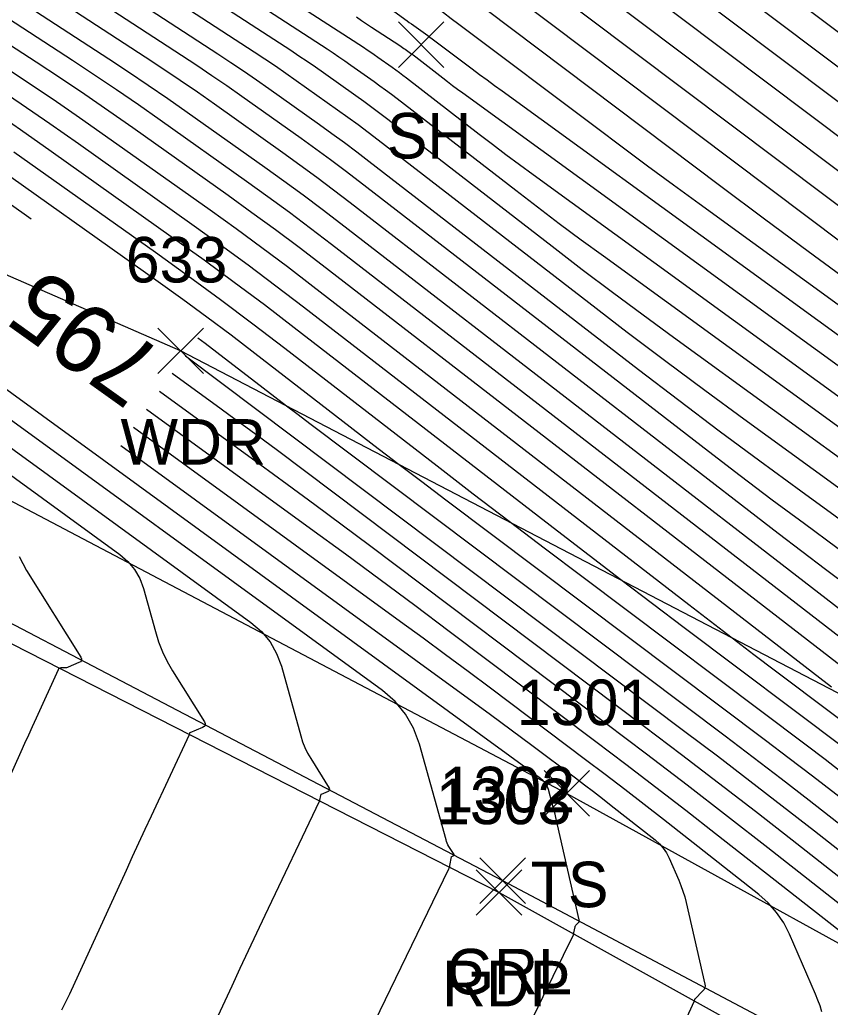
# Model space of a CAD drawing. Extents: x 1650836 to 1652450, y 332578 to 333908.
# Drawn here: x 1652211.55 to 1652247.14, y 332737.29 to 332780.66 of the extents above; entities that cross this region are included whole.
import ezdxf

# ---------------------------------------------------------------- set-up
doc = ezdxf.new("R2010")
doc.units = 0
for name, color, linetype in [('L_A', 7, 'Continuous'), ('L_I', 7, 'Continuous'), ('L_TIC', 7, 'Continuous'), ('LAWA', 7, 'Continuous'), ('LELB', 7, 'Continuous'), ('LSOGCMA', 7, 'Continuous'), ('LSOGCMA_T', 7, 'Continuous'), ('LSOGCMI', 7, 'Continuous'), ('P_A', 7, 'Continuous'), ('P_I', 7, 'Continuous'), ('P_TIC', 7, 'Continuous'), ('PET', 7, 'Continuous'), ('R_A', 7, 'Continuous'), ('R_I', 7, 'Continuous'), ('R_TIC', 7, 'Continuous'), ('RGR', 7, 'Continuous')]:
    doc.layers.add(name, color=color, linetype=linetype)

msp = doc.modelspace()

# ---------------------------------------------------------------- linework, layer by layer
at = {"layer": 'L_TIC'}
for points in [[(1652228.178, 332778.566), (1652230.178, 332780.566)], [(1652230.178, 332778.566), (1652228.178, 332780.566)], [(1652217.614, 332765.122), (1652219.614, 332767.122)], [(1652219.614, 332765.122), (1652217.614, 332767.122)], [(1652234.573, 332745.682), (1652236.573, 332747.682)], [(1652236.573, 332745.682), (1652234.573, 332747.682)]]:
    msp.add_lwpolyline(points, dxfattribs=at)
at = {"layer": 'LAWA'}
msp.add_lwpolyline([(1652408.76, 332665.713), (1652363.38, 332695.402), (1652324.46, 332714.991), (1652289.155, 332735.895), (1652253.497, 332747.946), (1652218.614, 332766.122), (1652198.198, 332775.017), (1652146.456, 332804.843), (1652136.841, 332807.592), (1652091.374, 332831.511), (1652057.601, 332848.138), (1652027.653, 332867.625)], dxfattribs=at)
at = {"layer": 'LELB'}
msp.add_lwpolyline([(1652023.441, 332859.649), (1652034.235, 332853.429), (1652052.246, 332842.357), (1652084.686, 332826.36), (1652123.711, 332804.04), (1652160.81, 332785.384), (1652195.281, 332767.897), (1652235.573, 332746.682), (1652255.289, 332735.81), (1652296.57, 332712.591), (1652348.8, 332686.345), (1652380.841, 332668.301), (1652404.073, 332656.539)], dxfattribs=at)
at = {"layer": 'LSOGCMA'}
for points in [[(1652207.289, 332796.117), (1652228.455, 332780.692), (1652228.555, 332780.619), (1652228.655, 332780.547), (1652228.756, 332780.475), (1652228.857, 332780.404), (1652229.261, 332780.119), (1652229.361, 332780.048), (1652229.462, 332779.976), (1652229.561, 332779.902), (1652229.66, 332779.829), (1652231.418, 332778.505), (1652231.744, 332778.261), (1652232.072, 332778.017), (1652232.4, 332777.776), (1652232.73, 332777.535), (1652253.597, 332762.371), (1652257.064, 332759.833), (1652260.514, 332757.272), (1652263.946, 332754.687), (1652267.36, 332752.078), (1652272.52, 332748.107)], [(1652250.989, 332750.892), (1652225.242, 332770.792), (1652224.318, 332771.499), (1652223.388, 332772.196), (1652222.45, 332772.884), (1652221.505, 332773.562), (1652217.711, 332776.256), (1652216.759, 332776.925), (1652215.801, 332777.584), (1652214.836, 332778.233), (1652213.865, 332778.873), (1652201.055, 332787.21)], [(1652254.883, 332736.054), (1652244.393, 332744.289), (1652242.627, 332745.668), (1652240.854, 332747.038), (1652239.074, 332748.398), (1652237.287, 332749.75), (1652226.901, 332757.565), (1652225.703, 332758.462), (1652224.502, 332759.355), (1652223.297, 332760.243), (1652222.088, 332761.126), (1652217.682, 332764.332)]]:
    msp.add_lwpolyline(points, dxfattribs=at)
at = {"layer": 'LSOGCMI'}
for points in [[(1652156.182, 332810.098), (1652168.54, 332801.315), (1652170.745, 332799.759), (1652172.961, 332798.219), (1652175.188, 332796.695), (1652177.426, 332795.187), (1652196.78, 332782.244), (1652197.703, 332781.629), (1652198.627, 332781.017), (1652199.554, 332780.407), (1652200.482, 332779.801), (1652204.2, 332777.381), (1652205.127, 332776.771), (1652206.047, 332776.152), (1652206.961, 332775.524), (1652207.868, 332774.887), (1652212.045, 332771.92)], [(1652211.623, 332803.175), (1652217.033, 332799.233), (1652218.387, 332798.25), (1652219.745, 332797.273), (1652221.107, 332796.301), (1652222.473, 332795.335), (1652230.674, 332789.557), (1652232.492, 332788.265), (1652234.299, 332786.96), (1652236.096, 332785.64), (1652237.883, 332784.306), (1652256.91, 332769.983), (1652257.734, 332769.367), (1652258.561, 332768.755), (1652259.391, 332768.148), (1652260.225, 332767.545), (1652263.567, 332765.145), (1652264.401, 332764.544), (1652265.235, 332763.941), (1652266.066, 332763.335)], [(1652211.433, 332801.854), (1652217.893, 332797.146), (1652219.455, 332796.013), (1652221.02, 332794.887), (1652222.59, 332793.766), (1652224.165, 332792.652), (1652230.472, 332788.209), (1652232.045, 332787.092), (1652233.608, 332785.962), (1652235.163, 332784.821), (1652236.708, 332783.667), (1652259.482, 332766.523), (1652259.982, 332766.149), (1652260.484, 332765.778), (1652260.988, 332765.409), (1652261.494, 332765.043), (1652263.522, 332763.586), (1652264.029, 332763.222), (1652264.535, 332762.855), (1652265.04, 332762.488), (1652265.544, 332762.12)], [(1652283.425, 332747.411), (1652264.19, 332761.511), (1652264.013, 332761.641), (1652263.835, 332761.77), (1652263.657, 332761.899), (1652263.478, 332762.028), (1652262.763, 332762.541), (1652262.585, 332762.67), (1652262.407, 332762.8), (1652262.23, 332762.931), (1652262.054, 332763.063), (1652235.533, 332783.027), (1652234.229, 332784.001), (1652232.917, 332784.964), (1652231.597, 332785.918), (1652230.27, 332786.86), (1652224.947, 332790.611), (1652223.618, 332791.551), (1652222.293, 332792.497), (1652220.971, 332793.448), (1652219.654, 332794.404), (1652211.167, 332800.588)], [(1652265.562, 332758.934), (1652263.87, 332760.236), (1652263.513, 332760.509), (1652263.153, 332760.78), (1652262.792, 332761.048), (1652262.428, 332761.314), (1652260.972, 332762.373), (1652260.608, 332762.638), (1652260.246, 332762.905), (1652259.884, 332763.174), (1652259.524, 332763.444), (1652234.359, 332782.387), (1652233.295, 332783.181), (1652232.226, 332783.967), (1652231.15, 332784.744), (1652230.068, 332785.512), (1652225.729, 332788.569), (1652224.645, 332789.336), (1652223.565, 332790.107), (1652222.488, 332790.882), (1652221.414, 332791.661), (1652210.191, 332799.84)], [(1652270.187, 332754.007), (1652264.784, 332758.165), (1652263.641, 332759.038), (1652262.493, 332759.903), (1652261.339, 332760.76), (1652260.179, 332761.609), (1652255.526, 332764.99), (1652254.365, 332765.837), (1652253.207, 332766.69), (1652252.053, 332767.547), (1652250.903, 332768.41), (1652233.184, 332781.748), (1652232.362, 332782.362), (1652231.535, 332782.969), (1652230.703, 332783.57), (1652229.866, 332784.164), (1652226.511, 332786.528), (1652225.673, 332787.121), (1652224.838, 332787.717), (1652224.005, 332788.316), (1652223.174, 332788.919), (1652209.215, 332799.092)], [(1652273.843, 332749.826), (1652265.697, 332756.094), (1652263.77, 332757.566), (1652261.833, 332759.025), (1652259.886, 332760.471), (1652257.929, 332761.904), (1652250.031, 332767.643), (1652248.097, 332769.055), (1652246.169, 332770.475), (1652244.246, 332771.903), (1652242.33, 332773.339), (1652232.009, 332781.108), (1652231.428, 332781.542), (1652230.844, 332781.971), (1652230.256, 332782.396), (1652229.665, 332782.816), (1652227.293, 332784.487), (1652226.701, 332784.906), (1652226.11, 332785.327), (1652225.521, 332785.751), (1652224.934, 332786.177), (1652208.765, 332797.96)], [(1652208.027, 332797.039), (1652226.695, 332783.434), (1652227.038, 332783.185), (1652227.383, 332782.937), (1652227.728, 332782.691), (1652228.075, 332782.445), (1652229.463, 332781.468), (1652229.809, 332781.222), (1652230.153, 332780.973), (1652230.495, 332780.722), (1652230.835, 332780.468), (1652236.874, 332775.922), (1652237.995, 332775.082), (1652239.12, 332774.246), (1652240.249, 332773.415), (1652241.38, 332772.589), (1652255.679, 332762.198), (1652258.433, 332760.183), (1652261.173, 332758.148), (1652263.899, 332756.095), (1652266.611, 332754.023), (1652273.182, 332748.967)], [(1652229.258, 332793.535), (1652231.078, 332792.253), (1652233.386, 332790.613), (1652235.681, 332788.956), (1652237.963, 332787.28), (1652240.232, 332785.586), (1652251.766, 332776.903), (1652253.237, 332775.802), (1652254.714, 332774.71), (1652256.197, 332773.625), (1652257.686, 332772.549), (1652263.655, 332768.262), (1652265.146, 332767.188), (1652266.635, 332766.111), (1652268.12, 332765.03), (1652269.603, 332763.946), (1652278.411, 332757.49), (1652280.207, 332756.153), (1652281.984, 332754.79), (1652283.741, 332753.403), (1652285.479, 332751.99), (1652294.014, 332744.946)], [(1652228.557, 332792.539), (1652230.876, 332790.905), (1652232.939, 332789.439), (1652234.99, 332787.958), (1652237.03, 332786.46), (1652239.057, 332784.946), (1652254.338, 332773.443), (1652255.485, 332772.584), (1652256.637, 332771.732), (1652257.794, 332770.887), (1652258.956, 332770.047), (1652263.611, 332766.703), (1652264.774, 332765.866), (1652265.935, 332765.026), (1652267.093, 332764.183), (1652268.25, 332763.337), (1652279.664, 332754.97), (1652281.251, 332753.789), (1652282.821, 332752.586), (1652284.373, 332751.36), (1652285.908, 332750.112), (1652293.336, 332743.982)], [(1652265.616, 332743.878), (1652264.402, 332744.786), (1652263.196, 332745.705), (1652258.389, 332749.404), (1652257.184, 332750.325), (1652255.973, 332751.237), (1652254.756, 332752.141), (1652253.532, 332753.037), (1652247.428, 332757.472), (1652246.006, 332758.514), (1652244.592, 332759.566), (1652243.185, 332760.628), (1652241.786, 332761.701), (1652226.474, 332773.537), (1652225.839, 332774.023), (1652225.199, 332774.502), (1652224.555, 332774.974), (1652223.905, 332775.44), (1652221.298, 332777.292), (1652220.644, 332777.751), (1652219.986, 332778.204), (1652219.323, 332778.65), (1652218.655, 332779.089), (1652201.299, 332790.386)], [(1652247.968, 332755.745), (1652246.924, 332756.522), (1652245.886, 332757.306), (1652244.854, 332758.098), (1652226.063, 332772.622), (1652225.332, 332773.181), (1652224.595, 332773.733), (1652223.853, 332774.277), (1652223.105, 332774.814), (1652220.103, 332776.947), (1652219.349, 332777.476), (1652218.591, 332777.997), (1652217.827, 332778.511), (1652217.058, 332779.017), (1652200.784, 332789.61)], [(1652200.477, 332788.698), (1652215.461, 332778.945), (1652216.332, 332778.372), (1652217.196, 332777.791), (1652218.054, 332777.2), (1652218.907, 332776.601), (1652222.305, 332774.188), (1652223.151, 332773.581), (1652223.991, 332772.965), (1652224.825, 332772.34), (1652225.653, 332771.707), (1652247.921, 332754.495)], [(1652205.286, 332788.903), (1652220.252, 332779.162), (1652220.818, 332778.789), (1652221.381, 332778.411), (1652221.939, 332778.027), (1652222.494, 332777.637), (1652224.705, 332776.066), (1652225.256, 332775.671), (1652225.803, 332775.27), (1652226.345, 332774.864), (1652226.884, 332774.452), (1652238.719, 332765.304), (1652240.484, 332763.95), (1652242.259, 332762.61), (1652244.044, 332761.282), (1652245.839, 332759.967), (1652253.541, 332754.37), (1652255.085, 332753.24), (1652256.622, 332752.099), (1652258.15, 332750.948), (1652259.671, 332749.786), (1652266.411, 332744.6)], [(1652269.948, 332743.246), (1652260.952, 332750.168), (1652259.116, 332751.571), (1652257.27, 332752.961), (1652255.415, 332754.339), (1652253.551, 332755.704), (1652243.35, 332763.116), (1652241.631, 332764.375), (1652239.921, 332765.647), (1652238.221, 332766.931), (1652236.53, 332768.228), (1652227.294, 332775.367), (1652226.852, 332775.705), (1652226.407, 332776.039), (1652225.958, 332776.368), (1652225.506, 332776.693), (1652223.69, 332777.982), (1652223.234, 332778.302), (1652222.776, 332778.617), (1652222.314, 332778.928), (1652221.849, 332779.234), (1652210.733, 332786.469)], [(1652252.445, 332748.534), (1652224.832, 332769.877), (1652223.812, 332770.658), (1652222.784, 332771.427), (1652221.748, 332772.187), (1652220.705, 332772.936), (1652216.515, 332775.911), (1652215.464, 332776.65), (1652214.406, 332777.377), (1652213.341, 332778.094), (1652212.268, 332778.8), (1652201.632, 332785.722)], [(1652273.485, 332741.892), (1652262.234, 332750.55), (1652260.082, 332752.194), (1652257.919, 332753.823), (1652255.745, 332755.438), (1652253.56, 332757.037), (1652240.262, 332766.7), (1652238.918, 332767.685), (1652237.58, 332768.68), (1652236.25, 332769.684), (1652234.928, 332770.699), (1652227.705, 332776.282), (1652227.359, 332776.546), (1652227.01, 332776.807), (1652226.659, 332777.065), (1652226.306, 332777.319), (1652224.886, 332778.327), (1652224.529, 332778.577), (1652224.171, 332778.824), (1652223.81, 332779.067), (1652223.446, 332779.306), (1652215.906, 332784.213)], [(1652219.604, 332782.919), (1652225.043, 332779.379), (1652225.305, 332779.206), (1652225.566, 332779.031), (1652225.824, 332778.853), (1652226.081, 332778.672), (1652227.106, 332777.945), (1652227.361, 332777.762), (1652227.614, 332777.576), (1652227.866, 332777.388), (1652228.115, 332777.197), (1652233.326, 332773.169), (1652234.28, 332772.437), (1652235.239, 332771.713), (1652236.204, 332770.995), (1652237.174, 332770.285), (1652253.569, 332758.371), (1652256.075, 332756.537), (1652258.568, 332754.686), (1652261.048, 332752.817), (1652263.515, 332750.932), (1652277.023, 332740.539)], [(1652223.301, 332781.624), (1652226.64, 332779.451), (1652226.801, 332779.345), (1652226.961, 332779.237), (1652227.119, 332779.128), (1652227.277, 332779.017), (1652227.906, 332778.571), (1652228.063, 332778.458), (1652228.218, 332778.344), (1652228.372, 332778.229), (1652228.525, 332778.112), (1652231.724, 332775.639), (1652232.31, 332775.19), (1652232.898, 332774.745), (1652233.491, 332774.305), (1652234.086, 332773.869), (1652253.578, 332759.704), (1652256.405, 332757.635), (1652259.216, 332755.548), (1652262.014, 332753.441), (1652264.797, 332751.314), (1652271.198, 332746.389)], [(1652226.329, 332780.784), (1652226.55, 332780.63), (1652226.773, 332780.478), (1652226.999, 332780.329), (1652228.237, 332779.523), (1652228.296, 332779.484), (1652228.356, 332779.444), (1652228.414, 332779.404), (1652228.473, 332779.362), (1652228.706, 332779.197), (1652228.764, 332779.155), (1652228.822, 332779.113), (1652228.879, 332779.07), (1652228.936, 332779.027), (1652230.122, 332778.11), (1652230.339, 332777.943), (1652230.558, 332777.778), (1652230.777, 332777.615), (1652230.998, 332777.453), (1652253.588, 332761.038), (1652256.734, 332758.734), (1652259.865, 332756.41), (1652262.98, 332754.064), (1652266.078, 332751.696)], [(1652210.671, 332778.728), (1652211.845, 332777.955), (1652213.011, 332777.171), (1652214.169, 332776.374), (1652215.32, 332775.566), (1652219.905, 332772.31), (1652221.046, 332771.49), (1652222.18, 332770.659), (1652223.305, 332769.816), (1652224.422, 332768.962), (1652246.683, 332751.756), (1652247.198, 332751.359)], [(1652210.349, 332777.816), (1652211.616, 332776.964), (1652212.874, 332776.099), (1652214.124, 332775.221), (1652219.104, 332771.684), (1652220.345, 332770.793), (1652221.576, 332769.89), (1652222.798, 332768.975), (1652224.011, 332768.047), (1652240.921, 332754.977), (1652241.872, 332754.245), (1652242.825, 332753.515), (1652243.781, 332752.789), (1652244.739, 332752.065), (1652249.624, 332748.39)], [(1652247.849, 332748.593), (1652240.727, 332753.953), (1652239.33, 332755.007), (1652237.936, 332756.067), (1652236.546, 332757.13), (1652235.159, 332758.199), (1652223.601, 332767.132), (1652222.292, 332768.134), (1652220.972, 332769.122), (1652219.643, 332770.096), (1652218.304, 332771.058), (1652212.928, 332774.876), (1652211.579, 332775.823), (1652210.221, 332776.757)], [(1652260.005, 332737.132), (1652256.345, 332739.743), (1652255.434, 332740.401), (1652254.531, 332741.069), (1652253.635, 332741.748), (1652252.747, 332742.437), (1652248.406, 332745.845), (1652247.386, 332746.642), (1652246.361, 332747.433), (1652245.333, 332748.219), (1652244.301, 332749), (1652230.256, 332759.567), (1652229.202, 332760.363), (1652228.151, 332761.162), (1652227.102, 332761.964), (1652226.056, 332762.77), (1652221.877, 332766), (1652220.828, 332766.803), (1652219.772, 332767.594), (1652218.707, 332768.375), (1652217.634, 332769.145), (1652209.582, 332774.864)], [(1652262.345, 332736.642), (1652261.203, 332737.468), (1652256.02, 332741.166), (1652255.173, 332741.778), (1652254.333, 332742.399), (1652253.501, 332743.03), (1652252.675, 332743.67), (1652249.388, 332746.25), (1652248.565, 332746.893), (1652247.738, 332747.532), (1652246.908, 332748.166), (1652246.075, 332748.797), (1652236.231, 332756.204), (1652234.636, 332757.408), (1652233.045, 332758.617), (1652231.458, 332759.831), (1652229.875, 332761.05), (1652223.19, 332766.217), (1652221.785, 332767.293), (1652220.369, 332768.353), (1652218.942, 332769.4), (1652217.504, 332770.432), (1652211.296, 332774.841)], [(1652203.206, 332766.441), (1652215.938, 332757.178), (1652216.297, 332756.87), (1652216.59, 332756.517), (1652216.818, 332756.119), (1652216.981, 332755.675), (1652217.505, 332753.788), (1652217.648, 332753.338), (1652217.821, 332752.901), (1652218.025, 332752.478), (1652218.261, 332752.069), (1652219.656, 332749.83), (1652219.692, 332749.748), (1652219.69, 332749.678), (1652219.651, 332749.62), (1652219.574, 332749.574), (1652219.015, 332749.339), (1652219.009, 332749.335), (1652219.004, 332749.33), (1652219.001, 332749.325), (1652218.999, 332749.318), (1652218.994, 332749.288), (1652218.992, 332749.281), (1652218.99, 332749.274), (1652218.987, 332749.267), (1652218.985, 332749.26), (1652217.322, 332745.688), (1652217.044, 332745.09), (1652216.768, 332744.492), (1652216.492, 332743.893), (1652216.218, 332743.293), (1652213.734, 332737.859), (1652213.386, 332737.163)], [(1652219.372, 332766.693), (1652219.692, 332766.453), (1652220.202, 332766.063), (1652222.237, 332764.49), (1652222.746, 332764.098), (1652223.257, 332763.707), (1652223.768, 332763.318), (1652224.281, 332762.931), (1652242.526, 332749.204), (1652243.758, 332748.272), (1652244.984, 332747.334), (1652246.206, 332746.39), (1652247.424, 332745.439), (1652253.393, 332740.753), (1652254.055, 332740.24), (1652254.723, 332739.733), (1652255.397, 332739.235), (1652256.077, 332738.744), (1652258.807, 332736.796)], [(1652205.418, 332766.035), (1652221.704, 332754.186), (1652222.163, 332753.792), (1652222.539, 332753.341), (1652222.83, 332752.831), (1652223.038, 332752.263), (1652223.886, 332749.212), (1652223.969, 332748.95), (1652224.07, 332748.696), (1652224.189, 332748.45), (1652224.326, 332748.212), (1652225.137, 332746.91), (1652225.158, 332746.862), (1652225.157, 332746.822), (1652225.134, 332746.788), (1652225.089, 332746.761), (1652224.79, 332746.635), (1652224.775, 332746.627), (1652224.763, 332746.616), (1652224.755, 332746.602), (1652224.75, 332746.585), (1652224.714, 332746.386), (1652224.711, 332746.371), (1652224.707, 332746.356), (1652224.702, 332746.341), (1652224.695, 332746.327), (1652222.318, 332741.323), (1652221.951, 332740.548), (1652221.584, 332739.771), (1652221.22, 332738.995), (1652220.856, 332738.217), (1652219.217, 332734.706)], [(1652226.911, 332736.183), (1652230.392, 332743.365), (1652230.408, 332743.401), (1652230.421, 332743.439), (1652230.432, 332743.476), (1652230.441, 332743.515), (1652230.51, 332743.9), (1652230.511, 332743.904), (1652230.513, 332743.908), (1652230.516, 332743.911), (1652230.521, 332743.913), (1652230.605, 332743.949), (1652230.617, 332743.956), (1652230.624, 332743.966), (1652230.624, 332743.977), (1652230.618, 332743.991), (1652230.391, 332744.356), (1652230.352, 332744.422), (1652230.319, 332744.491), (1652230.291, 332744.562), (1652230.267, 332744.636), (1652229.096, 332748.851), (1652228.843, 332749.543), (1652228.487, 332750.164), (1652228.03, 332750.715), (1652227.471, 332751.194), (1652207.63, 332765.629)], [(1652218.814, 332765.913), (1652218.821, 332765.907), (1652240.752, 332749.407), (1652242.182, 332748.325), (1652243.608, 332747.235), (1652245.027, 332746.138), (1652246.441, 332745.034), (1652254.039, 332739.07), (1652254.476, 332738.731), (1652254.916, 332738.397), (1652255.36, 332738.069), (1652255.809, 332737.745), (1652257.609, 332736.46)], [(1652234.097, 332736.847), (1652234.316, 332737.307), (1652234.538, 332737.764), (1652235.857, 332740.466), (1652235.866, 332740.487), (1652235.874, 332740.508), (1652235.881, 332740.53), (1652235.886, 332740.552), (1652235.937, 332740.828), (1652235.943, 332740.85), (1652235.952, 332740.871), (1652235.964, 332740.891), (1652235.98, 332740.909), (1652236.086, 332741.017), (1652236.106, 332741.042), (1652236.118, 332741.069), (1652236.122, 332741.098), (1652236.118, 332741.129), (1652235.089, 332745.617), (1652235.052, 332745.772), (1652235.014, 332745.927), (1652234.974, 332746.081), (1652234.932, 332746.234), (1652234.762, 332746.848), (1652234.708, 332746.994), (1652234.633, 332747.125), (1652234.537, 332747.241), (1652234.419, 332747.342), (1652209.842, 332765.223)], [(1652254.896, 332737.223), (1652254.685, 332737.386), (1652245.459, 332744.629), (1652243.848, 332745.886), (1652242.231, 332747.136), (1652240.607, 332748.377), (1652238.977, 332749.61), (1652222.861, 332761.736), (1652222.247, 332762.196), (1652221.632, 332762.654), (1652221.014, 332763.109), (1652220.394, 332763.561), (1652218.248, 332765.123)], [(1652250.632, 332737.152), (1652250.239, 332737.925), (1652249.76, 332738.633), (1652249.196, 332739.275), (1652248.547, 332739.851), (1652242.102, 332744.91), (1652240.795, 332745.931), (1652239.483, 332746.945), (1652238.165, 332747.953), (1652236.842, 332748.953), (1652230.41, 332753.793), (1652228.894, 332754.929), (1652227.374, 332756.058), (1652225.849, 332757.182), (1652224.319, 332758.3), (1652217.116, 332763.54)], [(1652246.77, 332737.083), (1652246.69, 332737.346), (1652246.598, 332737.605), (1652246.494, 332737.86), (1652245.349, 332740.496), (1652245.093, 332740.998), (1652244.783, 332741.457), (1652244.417, 332741.874), (1652243.995, 332742.248), (1652239.812, 332745.532), (1652238.963, 332746.195), (1652238.111, 332746.853), (1652237.256, 332747.507), (1652236.397, 332748.157), (1652232.222, 332751.298), (1652231.238, 332752.035), (1652230.251, 332752.769), (1652229.261, 332753.498), (1652228.268, 332754.224), (1652216.549, 332762.749)], [(1652215.983, 332761.958), (1652232.216, 332750.148), (1652232.673, 332749.814), (1652233.127, 332749.479), (1652233.581, 332749.142), (1652234.033, 332748.803), (1652235.952, 332747.36), (1652236.346, 332747.061), (1652236.739, 332746.761), (1652237.131, 332746.458), (1652237.521, 332746.154), (1652239.443, 332744.645), (1652239.637, 332744.473), (1652239.805, 332744.281), (1652239.948, 332744.07), (1652240.065, 332743.84), (1652240.483, 332742.877), (1652240.582, 332742.635), (1652240.67, 332742.388), (1652240.746, 332742.138), (1652240.81, 332741.885), (1652241.631, 332738.306), (1652241.641, 332738.223), (1652241.63, 332738.146), (1652241.598, 332738.074), (1652241.547, 332738.009), (1652241.188, 332737.644), (1652241.183, 332737.638), (1652241.178, 332737.632), (1652241.175, 332737.625), (1652241.173, 332737.617), (1652241.167, 332737.586), (1652241.166, 332737.578), (1652241.164, 332737.57), (1652241.161, 332737.563), (1652241.158, 332737.555), (1652240.264, 332735.612)], [(1652211.53, 332757.088), (1652211.681, 332756.776), (1652211.854, 332756.475), (1652214.226, 332752.667), (1652214.26, 332752.589), (1652214.258, 332752.523), (1652214.221, 332752.467), (1652214.148, 332752.424), (1652213.681, 332752.227), (1652213.642, 332752.213), (1652213.603, 332752.203), (1652213.563, 332752.196), (1652213.522, 332752.194), (1652213.356, 332752.193), (1652213.317, 332752.187), (1652213.285, 332752.173), (1652213.259, 332752.149), (1652213.239, 332752.116), (1652212.265, 332749.98), (1652212.097, 332749.611), (1652211.93, 332749.242), (1652211.764, 332748.873), (1652211.598, 332748.503), (1652208.576, 332741.752)]]:
    msp.add_lwpolyline(points, dxfattribs=at)
at = {"layer": 'P_TIC'}
for points in [[(1652231.596, 332741.33), (1652233.596, 332743.33)], [(1652233.596, 332741.33), (1652231.596, 332743.33)]]:
    msp.add_lwpolyline(points, dxfattribs=at)
at = {"layer": 'PET'}
msp.add_lwpolyline([(1651782.185, 332994.087), (1651800.504, 332980.945), (1651823.969, 332965.234), (1651861.092, 332941.311), (1651895.497, 332920.881), (1651932.1, 332899.878), (1651964.344, 332882.546), (1651997.084, 332865.287), (1652030.302, 332847.665), (1652049.548, 332837.673), (1652081.974, 332820.953), (1652121.026, 332800.401), (1652157.819, 332781.161), (1652191.945, 332763.077), (1652232.596, 332742.33), (1652251.93, 332731.59), (1652295.202, 332708.727), (1652345.726, 332682.336), (1652379.152, 332664.868), (1652402.111, 332652.828)], dxfattribs=at)
at = {"layer": 'R_TIC'}
for points in [[(1652231.753, 332741.853), (1652233.753, 332743.853)], [(1652233.753, 332741.853), (1652231.753, 332743.853)]]:
    msp.add_lwpolyline(points, dxfattribs=at)
at = {"layer": 'RGR'}
msp.add_lwpolyline([(1652023.441, 332859.649), (1652024.915, 332854.382), (1652030.806, 332848.332), (1652049.928, 332838.521), (1652082.838, 332821.514), (1652121.63, 332801.012), (1652157.949, 332781.905), (1652192.709, 332763.821), (1652232.753, 332742.853), (1652252.846, 332732.22), (1652295.713, 332710.152), (1652346.443, 332683.145), (1652379.801, 332666.008), (1652402.772, 332654.006)], dxfattribs=at)

# ---------------------------------------------------------------- texts
at = {"layer": 'L_A'}
for s, p in [('SH', (1652227.666, 332774.566)), ('WDR', (1652215.976, 332761.122)), ('TS', (1652233.983, 332741.682))]:
    msp.add_text(s, height=2, dxfattribs=at).set_placement(p)
at = {"layer": 'L_I'}
for s, p in [('633', (1652216.204, 332769.122)), ('1301', (1652233.369, 332749.682))]:
    msp.add_text(s, height=2, dxfattribs=at).set_placement(p)
at = {"layer": 'LSOGCMA_T'}
msp.add_text('795', height=3, rotation=144.4072, dxfattribs=at).set_placement((1652218.001, 332765.934))
at = {"layer": 'P_A'}
msp.add_text('RDP', height=2, dxfattribs=at).set_placement((1652230.084, 332737.33))
at = {"layer": 'P_I'}
msp.add_text('1303', height=2, dxfattribs=at).set_placement((1652229.825, 332745.33))
at = {"layer": 'R_A'}
msp.add_text('GRL', height=2, dxfattribs=at).set_placement((1652230.297, 332737.853))
at = {"layer": 'R_I'}
msp.add_text('1302', height=2, dxfattribs=at).set_placement((1652229.982, 332745.853))

doc.saveas('drawing.dxf')
